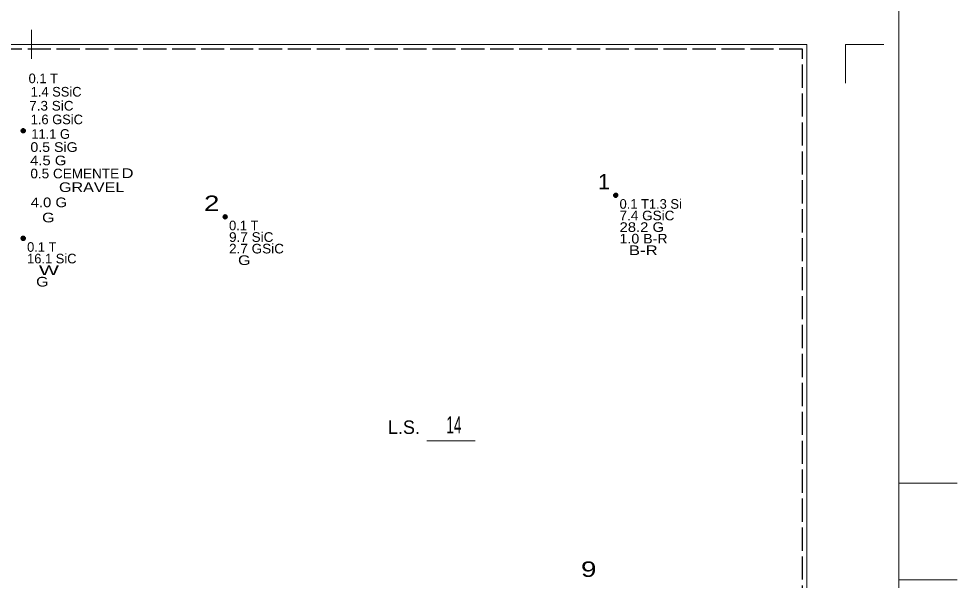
# Model space of a CAD drawing. Extents: x -496 to 480, y -450 to 700.
# Drawn here: x -6.6 to 480.3, y 124.7 to 415.7 of the extents above; entities that cross this region are included whole.
import ezdxf
from ezdxf.enums import TextEntityAlignment as Align

# ---------------------------------------------------------------- set-up
doc = ezdxf.new("R2010")
doc.units = 0
doc.header["$LTSCALE"] = 2
doc.linetypes.add('LONG_DASHED', pattern=[7.5, 6, -1.5])
doc.layers.add('1', color=7, linetype='Continuous', lineweight=13)
doc.layers.add('2', color=7, linetype='Continuous', lineweight=35)

msp = doc.modelspace()

# ---------------------------------------------------------------- linework, layer by layer
at = {"layer": '1'}
for p, q in [((-0.017, 394.973), (-0.017, 409.973)), ((422.281, 402.339), (442.281, 402.339)), ((422.281, 402.339), (422.281, 382.339)), ((205.122, 196.887), (230.122, 196.887)), ((480.331, 174.973), (449.983, 174.973)), ((480.331, 124.973), (449.983, 124.973))]:
    msp.add_line(p, q, dxfattribs=at)
for points in [[(449.983, -450.027), (449.983, 399.973), (449.983, 699.973), (-450.017, 699.973), (-450.017, 49.973), (-450.017, -450.027)], [(402.281, -402.333), (402.281, 402.339), (-402.391, 402.339)]]:
    msp.add_lwpolyline(points, dxfattribs=at)
at = {"layer": '2', "linetype": 'LONG_DASHED', "lineweight": 25}
msp.add_lwpolyline([(400, -400), (400, 400), (-302.391, 400)], dxfattribs=at)
at = {"layer": '2'}
for centre in [(-4.317, 357.711), (303.111, 324.24), (100.488, 313.083), (-4.317, 301.926)]:
    msp.add_circle(centre, 1, dxfattribs=at)
for points in [[(-4.328, 358.598), (-3.598, 358.194), (-3.446, 357.345), (-4.131, 356.817), (-4.94, 357.048), (-5.227, 357.806), (-4.98, 358.368), (-4.407, 358.536), (-3.733, 358.042), (-3.749, 357.3), (-4.266, 357.042), (-4.789, 357.211), (-5.013, 357.857), (-4.429, 358.323), (-3.991, 357.789), (-4.03, 357.306), (-4.659, 357.441), (-4.513, 358.076), (-4.221, 357.525)], [(303.1, 325.127), (303.83, 324.723), (303.982, 323.874), (303.297, 323.346), (302.488, 323.577), (302.201, 324.335), (302.448, 324.897), (303.021, 325.065), (303.695, 324.571), (303.679, 323.829), (303.162, 323.571), (302.639, 323.74), (302.415, 324.386), (302.999, 324.852), (303.437, 324.318), (303.398, 323.835), (302.769, 323.97), (302.915, 324.605), (303.207, 324.054)], [(100.477, 313.97), (101.207, 313.566), (101.359, 312.717), (100.674, 312.189), (99.865, 312.42), (99.578, 313.178), (99.825, 313.74), (100.398, 313.908), (101.072, 313.414), (101.056, 312.672), (100.539, 312.414), (100.016, 312.583), (99.792, 313.229), (100.376, 313.695), (100.814, 313.161), (100.775, 312.678), (100.146, 312.813), (100.292, 313.448), (100.584, 312.897)], [(-4.328, 302.813), (-3.598, 302.409), (-3.446, 301.56), (-4.131, 301.032), (-4.94, 301.263), (-5.227, 302.021), (-4.98, 302.583), (-4.407, 302.751), (-3.733, 302.257), (-3.749, 301.515), (-4.266, 301.257), (-4.789, 301.426), (-5.013, 302.072), (-4.429, 302.538), (-3.991, 302.004), (-4.03, 301.521), (-4.659, 301.656), (-4.513, 302.291), (-4.221, 301.74)]]:
    msp.add_spline(points, degree=3, dxfattribs=at)

# ---------------------------------------------------------------- texts
at = {"layer": '1', "width": 0.6}
msp.add_text('14', height=8.89, dxfattribs=at).set_placement((219.146, 200.791), align=Align.CENTER)
at = {"layer": '1'}
msp.add_text('L.S.', height=7, dxfattribs=at).set_placement((193.216, 200.511), align=Align.CENTER)
at = {"layer": '2'}
for s, p in [('0.1 T      ', (-1.538, 382.333)), ('1.4 SSiC   ', (-0.446, 375.398)), ('1.6 GSiC   ', (-0.446, 361.062)), ('11.1 G     ', (-0.134, 353.504)), ('0.1 T1.3 Si', (305.111, 317.24)), ('0.1 T      ', (102.488, 306.083)), ('0.1 T      ', (-2.317, 294.926)), ('16.1 SiC   ', (-2.317, 288.926))]:
    msp.add_text(s, height=5, dxfattribs=at).set_placement(p)
for s, width, p in [('7.3 SiC    ', 1.05, (-1.226, 368.152)), ('0.5 SiG    ', 1.1, (-0.602, 346.725)), ('4.5 G      ', 1.15, (-0.758, 339.79)), ('0.5 CEMENTE', 1.05, (-0.602, 333.012)), ('D          ', 1.3, (46.656, 333.177)), ('GRAVEL     ', 1.25, (14.218, 325.93)), ('4.0 G      ', 1.15, (-0.442, 318.061)), ('  G        ', 1.25, (0.806, 310.192)), ('7.4 GSiC   ', 1.05, (305.111, 311.24)), ('28.2 G     ', 1.15, (305.111, 305.24)), ('9.7 SiC    ', 1.05, (102.488, 300.083)), ('1.0 B-R    ', 1.1, (305.111, 299.24)), ('2.7 GSiC   ', 1.05, (102.488, 294.083)), ('  B-R      ', 1.3, (305.111, 293.24)), ('  G        ', 1.25, (102.488, 288.083)), ('  W        ', 1.65, (-2.317, 282.926)), ('  G        ', 1.25, (-2.317, 276.926))]:
    msp.add_text(s, height=5, dxfattribs=dict(at, width=width)).set_placement(p)
for s, width, p in [('  1', 1.05, (300.11, 327.24)), ('  2', 1.35, (97.487, 316.083)), ('  9', 1.35, (293.123, 126.414))]:
    msp.add_text(s, height=8, dxfattribs=dict(at, width=width)).set_placement(p, align=Align.RIGHT)

doc.saveas('drawing.dxf')
